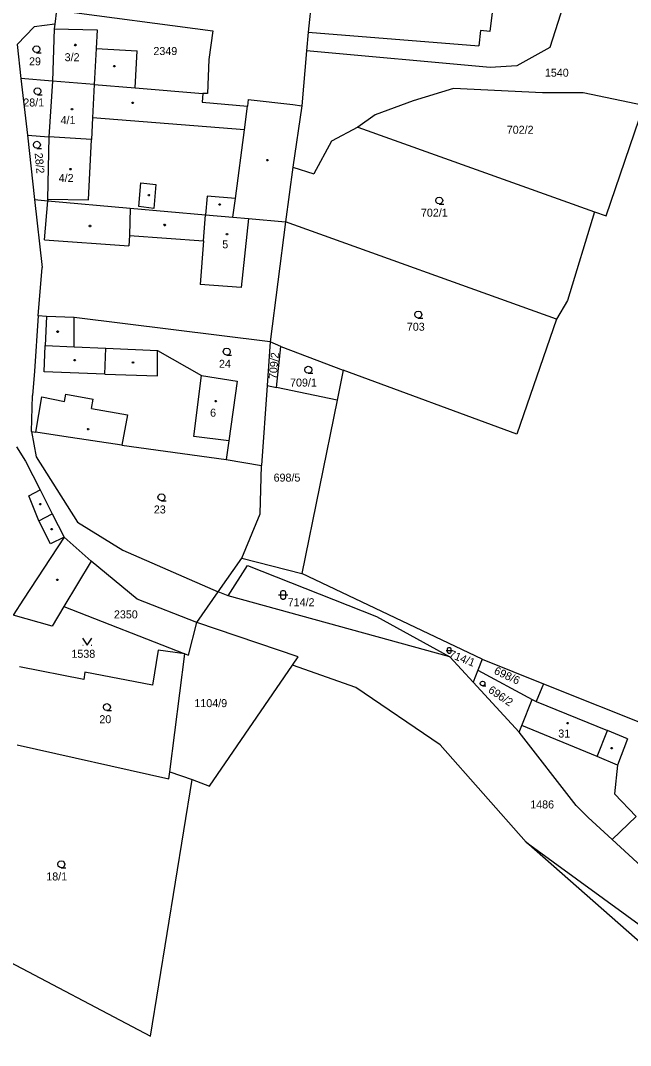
# Model space of a CAD drawing. Extents: x -852001 to -842497, y -1063614 to -1052182.
# Drawn here: x -850612.7 to -850483.1, y -1053699.4 to -1053481.6 of the extents above; entities that cross this region are included whole.
import ezdxf

# ---------------------------------------------------------------- set-up
doc = ezdxf.new("R2010")
doc.units = 0
for name, color, linetype in [('Default', 7, 'Continuous'), ('KN_HRANICE', 7, 'Continuous'), ('KN_KULTURY', 7, 'Continuous'), ('KN_PARCELY', 7, 'Continuous'), ('KN_SLUCKY', 7, 'Continuous')]:
    doc.layers.add(name, color=color, linetype=linetype)

# ---------------------------------------------------------------- blocks, each defined once
blk = doc.blocks.new('304')
at = {"layer": 'Default'}
blk.add_lwpolyline([(0, 0), (-0.38, 0.1), (-0.65, 0.37), (-0.75, 0.74), (-0.65, 1.11), (-0.38, 1.38), (-0.01, 1.48), (0.36, 1.38), (0.63, 1.11), (0.73, 0.73), (0.63, 0.35), (0.36, 0.08), (-0.02, -0.02), (0.98, -0.02)], dxfattribs=at)
blk = doc.blocks.new('314')
at = {"layer": 'Default'}
for p, q in [((-0.95, 0), (-0.85, 0)), ((0.85, 0), (0.95, 0))]:
    blk.add_line(p, q, dxfattribs=at)
blk.add_lwpolyline([(-1, 1.5), (0, 0), (1, 1.5)], dxfattribs=at)
blk = doc.blocks.new('316')
at = {"layer": 'Default'}
for points in [[(-1, 1), (0.27, 1), (1, 1)], [(-0.5, 1.5), (-0.4, 1.79), (-0.15, 1.97), (0.16, 1.97), (0.41, 1.79), (0.51, 1.5), (0.51, 0.5), (0.41, 0.21), (0.16, 0.03), (-0.15, 0.03), (-0.4, 0.21), (-0.5, 0.5), (-0.5, 1.5)]]:
    blk.add_lwpolyline(points, dxfattribs=at)
blk = doc.blocks.new('NAHRADNI_SYMBOL')
at = {"layer": 'Default'}
blk.add_lwpolyline([(0.09, 0.15), (0.18, 0), (0.09, -0.15), (-0.09, -0.15), (-0.18, 0), (-0.09, 0.15), (0.09, 0.15)], dxfattribs=at)
blk = doc.blocks.new('402')
at = {"layer": 'Default'}
blk.add_lwpolyline([(0.09, 0.15), (0.18, 0), (0.09, -0.15), (-0.09, -0.15), (-0.18, 0), (-0.09, 0.15), (0.09, 0.15)], dxfattribs=at)

msp = doc.modelspace()

# ---------------------------------------------------------------- linework, layer by layer
at = {"layer": 'KN_HRANICE'}
for p, q in [((-850495.1, -1053471.21), (-850500.17, -1053487.31)), ((-850550.56, -1053474.4), (-850551.52, -1053484.07)), ((-850605.06, -1053479.44), (-850605.41, -1053482.4)), ((-850605.06, -1053479.44), (-850571.78, -1053483.77)), ((-850512.46, -1053479.93), (-850512.92, -1053483.93)), ((-850609.81, -1053482.98), (-850613.39, -1053486.7)), ((-850605.41, -1053482.4), (-850609.81, -1053482.98)), ((-850605.52, -1053483.37), (-850605.87, -1053494.49)), ((-850605.41, -1053482.4), (-850605.52, -1053483.37)), ((-850605.52, -1053483.37), (-850596.37, -1053483.61)), ((-850596.37, -1053483.61), (-850596.6, -1053487.53)), ((-850571.78, -1053483.77), (-850572.66, -1053489.9)), ((-850551.52, -1053484.07), (-850551.93, -1053488.05)), ((-850551.52, -1053484.07), (-850515.29, -1053487.01)), ((-850514.91, -1053483.7), (-850515.29, -1053487.01)), ((-850512.92, -1053483.93), (-850514.91, -1053483.7)), ((-850613.39, -1053486.7), (-850612.58, -1053493.95)), ((-850596.6, -1053487.53), (-850587.87, -1053488.04)), ((-850500.17, -1053487.31), (-850507.22, -1053491.2)), ((-850588.33, -1053495.91), (-850587.87, -1053488.04)), ((-850572.66, -1053489.9), (-850572.94, -1053497.11)), ((-850551.93, -1053488.05), (-850552.89, -1053499.71)), ((-850512.86, -1053491.6), (-850551.93, -1053488.05)), ((-850507.22, -1053491.2), (-850512.86, -1053491.6)), ((-850605.87, -1053494.49), (-850612.58, -1053493.95)), ((-850612.58, -1053493.95), (-850611.23, -1053505.98)), ((-850605.87, -1053494.49), (-850606.64, -1053506.28)), ((-850597.02, -1053495.21), (-850605.87, -1053494.49)), ((-850597.02, -1053495.21), (-850588.33, -1053495.91)), ((-850588.33, -1053495.91), (-850573.91, -1053497.08)), ((-850520.64, -1053496.07), (-850529.27, -1053498.69)), ((-850501.73, -1053496.94), (-850520.64, -1053496.07)), ((-850573.91, -1053497.08), (-850574.07, -1053498.98)), ((-850572.94, -1053497.11), (-850573.91, -1053497.08)), ((-850564.28, -1053498.36), (-850564.43, -1053499.83)), ((-850564.28, -1053498.36), (-850554.83, -1053499.43)), ((-850529.27, -1053498.69), (-850537.35, -1053501.64)), ((-850493.13, -1053497), (-850501.73, -1053496.94)), ((-850480.2, -1053499.68), (-850493.13, -1053497)), ((-850574.07, -1053498.98), (-850564.43, -1053499.83)), ((-850554.83, -1053499.43), (-850552.89, -1053499.71)), ((-850552.89, -1053499.71), (-850554.83, -1053512.79)), ((-850488.23, -1053523.1), (-850480.2, -1053499.68)), ((-850537.35, -1053501.64), (-850540.97, -1053504.23)), ((-850540.97, -1053504.23), (-850546.58, -1053507.26)), ((-850540.97, -1053504.23), (-850490.71, -1053522.25)), ((-850611.23, -1053505.98), (-850609.7, -1053519.63)), ((-850611.23, -1053505.98), (-850606.64, -1053506.28)), ((-850606.64, -1053506.28), (-850606.98, -1053519.55)), ((-850597.6, -1053506.87), (-850606.64, -1053506.28)), ((-850598.23, -1053519.71), (-850597.6, -1053506.87)), ((-850546.58, -1053507.26), (-850550.37, -1053514.19)), ((-850554.83, -1053512.79), (-850556.37, -1053524.38)), ((-850554.83, -1053512.79), (-850550.37, -1053514.19)), ((-850609.7, -1053519.63), (-850606.88, -1053519.88)), ((-850609.7, -1053519.63), (-850608.08, -1053534.07)), ((-850606.98, -1053519.55), (-850606.88, -1053519.88)), ((-850606.98, -1053519.55), (-850598.23, -1053519.71)), ((-850606.88, -1053519.88), (-850589.35, -1053521.44)), ((-850589.35, -1053521.44), (-850573.38, -1053522.86)), ((-850573.38, -1053522.86), (-850567.55, -1053523.38)), ((-850490.71, -1053522.25), (-850496.45, -1053541.11)), ((-850490.71, -1053522.25), (-850488.23, -1053523.1)), ((-850567.55, -1053523.38), (-850564.24, -1053523.67)), ((-850564.24, -1053523.67), (-850556.37, -1053524.38)), ((-850556.37, -1053524.38), (-850559.65, -1053549.88)), ((-850498.75, -1053545.06), (-850556.37, -1053524.38)), ((-850608.92, -1053544.34), (-850608.08, -1053534.07)), ((-850496.45, -1053541.11), (-850498.75, -1053545.06)), ((-850608.92, -1053544.34), (-850609.68, -1053556.12)), ((-850607.17, -1053544.47), (-850608.92, -1053544.34)), ((-850601.28, -1053544.72), (-850607.17, -1053544.47)), ((-850559.65, -1053549.88), (-850601.28, -1053544.72)), ((-850601.25, -1053550.93), (-850601.28, -1053544.72)), ((-850498.75, -1053545.06), (-850507.22, -1053569.51)), ((-850601.25, -1053550.93), (-850594.55, -1053551.21)), ((-850559.65, -1053549.88), (-850560.28, -1053559.12)), ((-850557.34, -1053550.88), (-850559.65, -1053549.88)), ((-850558.27, -1053559.54), (-850557.34, -1053550.88)), ((-850557.34, -1053550.88), (-850544.12, -1053555.88)), ((-850594.55, -1053551.21), (-850583.56, -1053551.68)), ((-850583.56, -1053551.68), (-850574.24, -1053556.99)), ((-850609.68, -1053556.12), (-850610.14, -1053561.27)), ((-850574.24, -1053556.99), (-850566.62, -1053558.23)), ((-850544.12, -1053555.88), (-850545.42, -1053562.28)), ((-850507.22, -1053569.51), (-850544.12, -1053555.88)), ((-850566.62, -1053558.23), (-850568.43, -1053570.88)), ((-850560.28, -1053559.12), (-850561.44, -1053576.17)), ((-850560.28, -1053559.12), (-850558.27, -1053559.54)), ((-850545.42, -1053562.28), (-850558.27, -1053559.54)), ((-850610.32, -1053568.9), (-850610.14, -1053561.27)), ((-850545.42, -1053562.28), (-850552.92, -1053599.08)), ((-850610.32, -1053568.9), (-850609.43, -1053569.03)), ((-850610.32, -1053568.9), (-850609.38, -1053574.28)), ((-850603.51, -1053570), (-850609.43, -1053569.03)), ((-850591.16, -1053571.79), (-850603.51, -1053570)), ((-850613.54, -1053572.2), (-850611.6, -1053575.23)), ((-850591.16, -1053571.79), (-850569, -1053574.9)), ((-850568.43, -1053570.88), (-850569, -1053574.9)), ((-850609.38, -1053574.28), (-850600.56, -1053588.2)), ((-850569, -1053574.9), (-850561.44, -1053576.17)), ((-850611.6, -1053575.23), (-850608.5, -1053581.34)), ((-850561.72, -1053586.38), (-850561.44, -1053576.17)), ((-850608.5, -1053581.34), (-850605.92, -1053586.42)), ((-850605.92, -1053586.42), (-850603.43, -1053591.33)), ((-850600.56, -1053588.2), (-850590.91, -1053594.16)), ((-850565.66, -1053595.86), (-850561.72, -1053586.38)), ((-850597.64, -1053596.49), (-850603.43, -1053591.33)), ((-850590.91, -1053594.16), (-850570.67, -1053603.01)), ((-850597.64, -1053596.49), (-850603.51, -1053606.11)), ((-850587.92, -1053604.52), (-850597.64, -1053596.49)), ((-850570.67, -1053603.01), (-850565.66, -1053595.86)), ((-850565.66, -1053595.86), (-850552.92, -1053599.08)), ((-850568.53, -1053603.83), (-850564.48, -1053597.38)), ((-850564.48, -1053597.38), (-850537.04, -1053608.24)), ((-850514.55, -1053617.3), (-850552.92, -1053599.08)), ((-850575.2, -1053609.48), (-850570.67, -1053603.01)), ((-850568.53, -1053603.83), (-850570.67, -1053603.01)), ((-850575.2, -1053609.48), (-850587.92, -1053604.52)), ((-850521.46, -1053616.8), (-850568.53, -1053603.83)), ((-850603.51, -1053606.11), (-850605.98, -1053610.26)), ((-850603.51, -1053606.11), (-850577.79, -1053616.12)), ((-850605.98, -1053610.26), (-850614.24, -1053607.97)), ((-850576.99, -1053616.43), (-850575.2, -1053609.48)), ((-850553.68, -1053616.8), (-850575.2, -1053609.48)), ((-850537.04, -1053608.24), (-850521.46, -1053616.8)), ((-850583.4, -1053615.39), (-850584.6, -1053622.84)), ((-850577.79, -1053616.12), (-850583.4, -1053615.39)), ((-850580.98, -1053641.2), (-850577.79, -1053616.12)), ((-850577.79, -1053616.12), (-850576.99, -1053616.43)), ((-850572.54, -1053644.27), (-850554.91, -1053618.59)), ((-850554.91, -1053618.59), (-850553.68, -1053616.8)), ((-850541.46, -1053623.3), (-850554.91, -1053618.59)), ((-850516.5, -1053622.17), (-850521.46, -1053616.8)), ((-850514.55, -1053617.3), (-850515.48, -1053619.62)), ((-850514.55, -1053617.3), (-850501.57, -1053622.5)), ((-850599.25, -1053621.58), (-850612.93, -1053618.93)), ((-850599, -1053620.06), (-850599.25, -1053621.58)), ((-850584.6, -1053622.84), (-850599, -1053620.06)), ((-850515.48, -1053619.62), (-850516.5, -1053622.17)), ((-850515.48, -1053619.62), (-850503.95, -1053625.86)), ((-850516.5, -1053622.17), (-850506.73, -1053632.76)), ((-850501.57, -1053622.5), (-850503.12, -1053626.3)), ((-850501.57, -1053622.5), (-850462.18, -1053638.28)), ((-850523.5, -1053635.48), (-850541.46, -1053623.3)), ((-850506.18, -1053631.4), (-850503.95, -1053625.86)), ((-850503.95, -1053625.86), (-850503.12, -1053626.3)), ((-850503.12, -1053626.3), (-850487.95, -1053632.45)), ((-850506.73, -1053632.76), (-850506.18, -1053631.4)), ((-850494.64, -1053648.37), (-850506.73, -1053632.76)), ((-850483.67, -1053634.23), (-850487.95, -1053632.45)), ((-850613.39, -1053635.48), (-850581.18, -1053642.71)), ((-850505.26, -1053656.14), (-850523.5, -1053635.48)), ((-850483.67, -1053634.23), (-850485.83, -1053639.78)), ((-850485.83, -1053639.78), (-850486.44, -1053645.86)), ((-850581.18, -1053642.71), (-850580.98, -1053641.2)), ((-850580.98, -1053641.2), (-850576.19, -1053642.88)), ((-850585.08, -1053697.36), (-850576.19, -1053642.88)), ((-850576.19, -1053642.88), (-850572.54, -1053644.27)), ((-850486.44, -1053645.86), (-850481.82, -1053650.71)), ((-850492.05, -1053650.95), (-850494.64, -1053648.37)), ((-850492.05, -1053650.95), (-850486.95, -1053655.61)), ((-850486.95, -1053655.61), (-850481.82, -1053650.71)), ((-850476.59, -1053665.13), (-850486.95, -1053655.61)), ((-850456.22, -1053699.36), (-850505.26, -1053656.14)), ((-850505.26, -1053656.14), (-850454.26, -1053693.33)), ((-850641.71, -1053667.54), (-850585.08, -1053697.36))]:
    msp.add_line(p, q, dxfattribs=at)
at = {"layer": 'KN_SLUCKY'}
for p, q in [((-850596.6, -1053487.53), (-850597.02, -1053495.21)), ((-850597.02, -1053495.21), (-850597.37, -1053502.28)), ((-850565.06, -1053504.83), (-850564.43, -1053499.83)), ((-850597.37, -1053502.28), (-850597.6, -1053506.87)), ((-850565.06, -1053504.83), (-850597.37, -1053502.28)), ((-850567, -1053519.43), (-850565.06, -1053504.83)), ((-850587.53, -1053521.15), (-850587.13, -1053516.08)), ((-850587.13, -1053516.08), (-850583.93, -1053516.41)), ((-850583.93, -1053516.41), (-850584.33, -1053521.55)), ((-850607.6, -1053528.17), (-850606.88, -1053519.88)), ((-850573.03, -1053518.9), (-850573.38, -1053522.86)), ((-850567, -1053519.43), (-850573.03, -1053518.9)), ((-850567.55, -1053523.38), (-850567, -1053519.43)), ((-850589.35, -1053521.44), (-850589.51, -1053527.26)), ((-850584.33, -1053521.55), (-850587.53, -1053521.15)), ((-850573.79, -1053528.43), (-850573.38, -1053522.86)), ((-850564.24, -1053523.67), (-850565.81, -1053538.34)), ((-850607.6, -1053528.17), (-850589.68, -1053529.5)), ((-850589.51, -1053527.26), (-850589.68, -1053529.5)), ((-850589.51, -1053527.26), (-850573.79, -1053528.43)), ((-850573.79, -1053528.43), (-850574.48, -1053537.7)), ((-850565.81, -1053538.34), (-850574.48, -1053537.7)), ((-850607.17, -1053544.47), (-850607.44, -1053550.66)), ((-850607.68, -1053556.25), (-850607.44, -1053550.66)), ((-850607.44, -1053550.66), (-850601.25, -1053550.93)), ((-850594.76, -1053556.72), (-850594.55, -1053551.21)), ((-850583.58, -1053557.1), (-850583.56, -1053551.68)), ((-850594.76, -1053556.72), (-850607.68, -1053556.25)), ((-850594.76, -1053556.72), (-850583.58, -1053557.1)), ((-850575.86, -1053569.95), (-850574.24, -1053556.99)), ((-850609.43, -1053569.03), (-850608.15, -1053561.53)), ((-850608.15, -1053561.53), (-850603.3, -1053562.53)), ((-850603.3, -1053562.53), (-850603.04, -1053561.02)), ((-850603.04, -1053561.02), (-850597.26, -1053562.05)), ((-850597.6, -1053564.03), (-850597.26, -1053562.05)), ((-850597.6, -1053564.03), (-850589.93, -1053565.41)), ((-850589.93, -1053565.41), (-850591.16, -1053571.79)), ((-850568.43, -1053570.88), (-850575.86, -1053569.95)), ((-850610.91, -1053582.56), (-850608.5, -1053581.34)), ((-850608.82, -1053587.9), (-850610.91, -1053582.56)), ((-850608.82, -1053587.9), (-850605.92, -1053586.42)), ((-850606.33, -1053592.8), (-850608.82, -1053587.9)), ((-850603.43, -1053591.33), (-850612.02, -1053604.55)), ((-850603.43, -1053591.33), (-850606.33, -1053592.8)), ((-850612.02, -1053604.55), (-850614.24, -1053607.97)), ((-850490.11, -1053637.94), (-850506.18, -1053631.4)), ((-850490.11, -1053637.94), (-850487.95, -1053632.45)), ((-850485.83, -1053639.78), (-850490.11, -1053637.94))]:
    msp.add_line(p, q, dxfattribs=at)

# ---------------------------------------------------------------- block references
at = {"layer": 'KN_KULTURY'}
for name, p in [('304', (-850609.29, -1053488.43)), ('402', (-850601.01, -1053486.8)), ('402', (-850592.74, -1053491.28)), ('304', (-850609.06, -1053497.35)), ('402', (-850601.75, -1053500.42)), ('402', (-850588.84, -1053499.09)), ('304', (-850609.19, -1053508.74)), ('402', (-850560.2, -1053511.29)), ('NAHRADNI_SYMBOL', (-850602.06, -1053513.21)), ('402', (-850585.4, -1053518.73)), ('402', (-850570.36, -1053520.69)), ('304', (-850523.7, -1053520.58)), ('402', (-850582.02, -1053525.05)), ('402', (-850597.91, -1053525.26)), ('402', (-850568.81, -1053526.98)), ('304', (-850528.15, -1053544.81)), ('402', (-850604.78, -1053547.7)), ('304', (-850568.85, -1053552.69)), ('402', (-850601.17, -1053553.76)), ('402', (-850588.78, -1053554.26)), ('304', (-850551.51, -1053556.53)), ('402', (-850571.19, -1053562.47)), ('402', (-850598.32, -1053568.4)), ('304', (-850582.73, -1053583.63)), ('402', (-850608.49, -1053584.36)), ('402', (-850606.06, -1053589.67)), ('402', (-850604.84, -1053600.42)), ('316', (-850556.86, -1053604.64)), ('314', (-850598.5, -1053614.29)), ('304', (-850594.31, -1053628.19)), ('402', (-850496.44, -1053630.87)), ('402', (-850487.05, -1053636.19)), ('304', (-850604, -1053661.6))]:
    msp.add_blockref(name, p, dxfattribs=at)
at = {"layer": 'KN_KULTURY', "xscale": 0.67, "yscale": 0.67}
for name, p in [('316', (-850521.58, -1053616.1)), ('304', (-850514.47, -1053622.95))]:
    msp.add_blockref(name, p, dxfattribs=at)

# ---------------------------------------------------------------- texts
at = {"layer": 'KN_PARCELY'}
for s, p in [('2349', (-850584.44, -1053488.94)), ('29', (-850610.87, -1053491.13)), ('3/2', (-850603.3, -1053490.25)), ('1540', (-850501.25, -1053493.54)), ('28/1', (-850612.09, -1053499.87)), ('4/1', (-850604.17, -1053503.62)), ('702/2', (-850509.35, -1053505.66)), ('4/2', (-850604.57, -1053515.91)), ('702/1', (-850527.59, -1053523.28)), ('5', (-850569.81, -1053530)), ('703', (-850530.58, -1053547.51)), ('24', (-850570.51, -1053555.39)), ('709/1', (-850555.4, -1053559.37)), ('6', (-850572.39, -1053565.77)), ('698/5', (-850558.9, -1053579.56)), ('23', (-850584.35, -1053586.33)), ('714/2', (-850555.9, -1053606.04)), ('2350', (-850592.83, -1053608.62)), ('1538', (-850601.86, -1053616.99)), ('1104/9', (-850575.73, -1053627.47)), ('20', (-850595.93, -1053630.89)), ('31', (-850498.4, -1053633.93)), ('1486', (-850504.36, -1053649)), ('18/1', (-850607.2, -1053664.3))]:
    msp.add_text(s, height=1.7, dxfattribs=at).set_placement(p)
for s, rotation, p in [('28/2', 275.364, (-850609.68, -1053509.8)), ('709/2', 84.798, (-850558.27, -1053557.85)), ('714/1', 338.618, (-850521.79, -1053616.84)), ('698/6', 335.066, (-850512.22, -1053620.33)), ('696/2', 325.841, (-850513.46, -1053624.2))]:
    msp.add_text(s, height=1.7, rotation=rotation, dxfattribs=at).set_placement(p)

doc.saveas('drawing.dxf')
